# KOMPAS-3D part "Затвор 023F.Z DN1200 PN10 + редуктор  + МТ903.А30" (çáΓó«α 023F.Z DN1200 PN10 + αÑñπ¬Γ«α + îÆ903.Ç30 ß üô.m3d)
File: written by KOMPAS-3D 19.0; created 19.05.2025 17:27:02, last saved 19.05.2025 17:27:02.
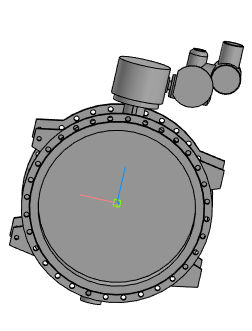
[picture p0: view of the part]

Document properties: Полное имя файла: Затвор 023F.Z DN1200 PN10 + редуктор + МТ903.А30 с БУ.a3d

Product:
- Part/product: Затвор 023F.Z DN1200 PN10 + редуктор  + МТ903.А30
    Масса: 2348.69

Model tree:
1. Операция без истории:1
